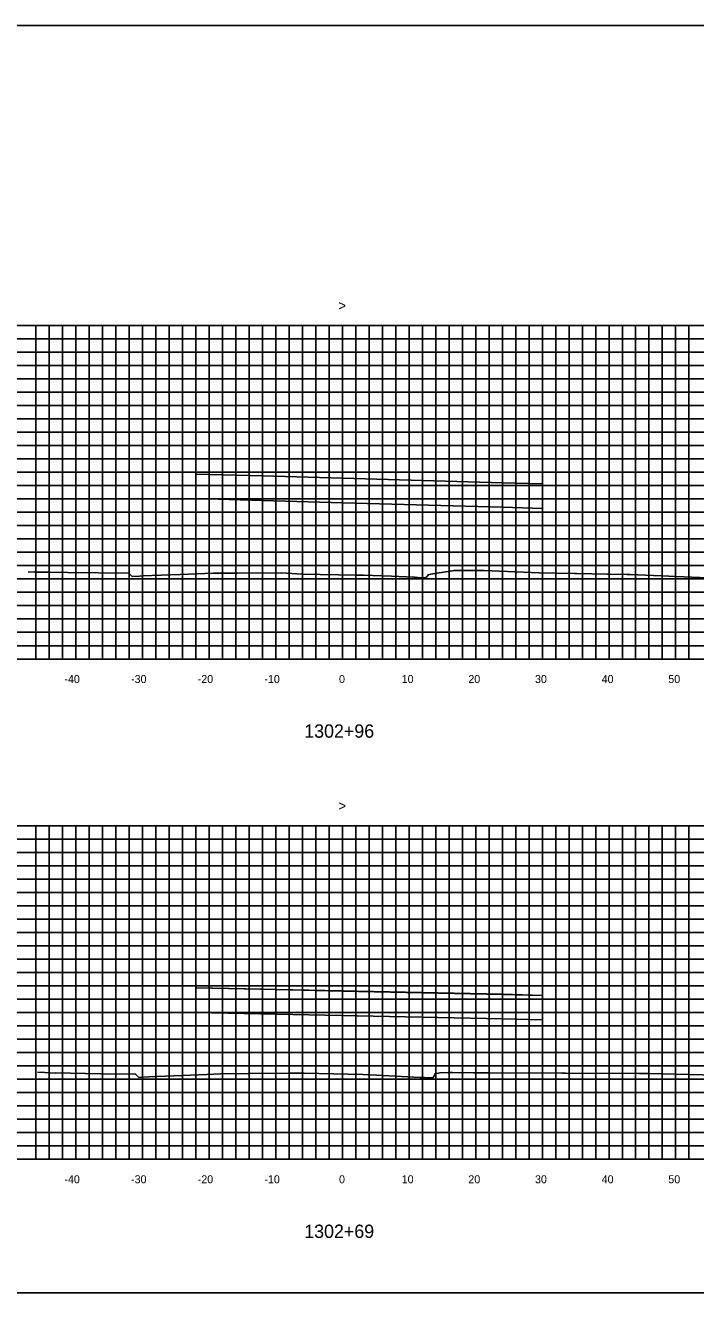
# Model space of a CAD drawing. Extents: x 1797714 to 1804825, y 249015 to 250269.
# Drawn here: x 1802923.4 to 1803024, y 250079.4 to 250269.4 of the extents above; entities that cross this region are included whole.
import ezdxf

# ---------------------------------------------------------------- set-up
doc = ezdxf.new("R2010")
doc.units = 0
for name, color, linetype in [('1', 7, 'Continuous'), ('10', 7, 'Continuous'), ('60', 7, 'Continuous'), ('BRG-DECK', 7, 'Continuous'), ('CL-CNST', 7, 'Continuous'), ('Level 62', 7, 'Continuous'), ('M-ROADS', 7, 'Continuous')]:
    doc.layers.add(name, color=color, linetype=linetype)

msp = doc.modelspace()

# ---------------------------------------------------------------- linework, layer by layer
for p, q in [((1802971, 250201.54), (1802971, 250203.54)), ((1802971, 250124.65), (1802971, 250126.65))]:
    msp.add_line(p, q)
msp.add_lwpolyline([(1802821, 250079.43), (1803121, 250079.43), (1803121, 250269.43), (1802821, 250269.43)], close=True)
at = {"layer": '60'}
for p, q in [((1802821, 250174.43), (1803121, 250174.43)), ((1802931, 250174.37), (1802931, 250174.43)), ((1802941, 250174.37), (1802941, 250174.43)), ((1802951, 250174.37), (1802951, 250174.43)), ((1802961, 250174.37), (1802961, 250174.43)), ((1802971, 250174.37), (1802971, 250174.43)), ((1802981, 250174.37), (1802981, 250174.43)), ((1802991, 250174.37), (1802991, 250174.43)), ((1803001, 250174.37), (1803001, 250174.43)), ((1803011, 250174.37), (1803011, 250174.43)), ((1803021, 250174.37), (1803021, 250174.43)), ((1802821, 250099.43), (1803121, 250099.43)), ((1802931, 250099.37), (1802931, 250099.43)), ((1802941, 250099.37), (1802941, 250099.43)), ((1802951, 250099.37), (1802951, 250099.43)), ((1802961, 250099.37), (1802961, 250099.43)), ((1802971, 250099.37), (1802971, 250099.43)), ((1802981, 250099.37), (1802981, 250099.43)), ((1802991, 250099.37), (1802991, 250099.43)), ((1803001, 250099.37), (1803001, 250099.43)), ((1803011, 250099.37), (1803011, 250099.43)), ((1803021, 250099.37), (1803021, 250099.43))]:
    msp.add_line(p, q, dxfattribs=at)
at = {"layer": 'BRG-DECK'}
for points in [[(1803001, 250197), (1803001, 250200.68), (1802995, 250200.86), (1802971, 250201.54), (1802959, 250201.88), (1802949, 250202.16), (1802949, 250198.48), (1802959, 250198.2), (1802971, 250197.86), (1802995, 250197.18)], [(1803001, 250120.31), (1803001, 250123.99), (1802995, 250124.17), (1802949, 250125.13), (1802949, 250121.45), (1802995, 250120.49)]]:
    msp.add_lwpolyline(points, close=True, dxfattribs=at)
at = {"layer": 'CL-CNST'}
for points in [[(1802949, 250202.16), (1802959, 250201.88), (1802971, 250201.54), (1802995, 250200.85), (1803001, 250200.68)], [(1802949, 250125.13), (1802959, 250124.91), (1802971, 250124.65), (1802995, 250124.12), (1803001, 250123.99)]]:
    msp.add_lwpolyline(points, dxfattribs=at)
at = {"layer": 'Level 62'}
for p, q in [((1802821, 250224.43), (1803121, 250224.43)), ((1802925, 250174.43), (1802925, 250224.43)), ((1802927, 250174.43), (1802927, 250224.43)), ((1802929, 250174.43), (1802929, 250224.43)), ((1802931, 250174.43), (1802931, 250224.43)), ((1802933, 250174.43), (1802933, 250224.43)), ((1802935, 250174.43), (1802935, 250224.43)), ((1802937, 250174.43), (1802937, 250224.43)), ((1802939, 250174.43), (1802939, 250224.43)), ((1802941, 250174.43), (1802941, 250224.43)), ((1802943, 250174.43), (1802943, 250224.43)), ((1802945, 250174.43), (1802945, 250224.43)), ((1802947, 250174.43), (1802947, 250224.43)), ((1802949, 250174.43), (1802949, 250224.43)), ((1802951, 250174.43), (1802951, 250224.43)), ((1802953, 250174.43), (1802953, 250224.43)), ((1802955, 250174.43), (1802955, 250224.43)), ((1802957, 250174.43), (1802957, 250224.43)), ((1802959, 250174.43), (1802959, 250224.43)), ((1802961, 250174.43), (1802961, 250224.43)), ((1802963, 250174.43), (1802963, 250224.43)), ((1802965, 250174.43), (1802965, 250224.43)), ((1802967, 250174.43), (1802967, 250224.43)), ((1802969, 250174.43), (1802969, 250224.43)), ((1802971, 250174.43), (1802971, 250224.43)), ((1802973, 250174.43), (1802973, 250224.43)), ((1802975, 250174.43), (1802975, 250224.43)), ((1802977, 250174.43), (1802977, 250224.43)), ((1802979, 250174.43), (1802979, 250224.43)), ((1802981, 250174.43), (1802981, 250224.43)), ((1802983, 250174.43), (1802983, 250224.43)), ((1802985, 250174.43), (1802985, 250224.43)), ((1802987, 250174.43), (1802987, 250224.43)), ((1802989, 250174.43), (1802989, 250224.43)), ((1802991, 250174.43), (1802991, 250224.43)), ((1802993, 250174.43), (1802993, 250224.43)), ((1802995, 250174.43), (1802995, 250224.43)), ((1802997, 250174.43), (1802997, 250224.43)), ((1802999, 250174.43), (1802999, 250224.43)), ((1803001, 250174.43), (1803001, 250224.43)), ((1803003, 250174.43), (1803003, 250224.43)), ((1803005, 250174.43), (1803005, 250224.43)), ((1803007, 250174.43), (1803007, 250224.43)), ((1803009, 250174.43), (1803009, 250224.43)), ((1803011, 250174.43), (1803011, 250224.43)), ((1803013, 250174.43), (1803013, 250224.43)), ((1803015, 250174.43), (1803015, 250224.43)), ((1803017, 250174.43), (1803017, 250224.43)), ((1803019, 250174.43), (1803019, 250224.43)), ((1803021, 250174.43), (1803021, 250224.43)), ((1803023, 250174.43), (1803023, 250224.43)), ((1802821, 250222.43), (1803121, 250222.43)), ((1802821, 250220.43), (1803121, 250220.43)), ((1802821, 250218.43), (1803121, 250218.43)), ((1802821, 250216.43), (1803121, 250216.43)), ((1802821, 250214.43), (1803121, 250214.43)), ((1802821, 250212.43), (1803121, 250212.43)), ((1802821, 250210.43), (1803121, 250210.43)), ((1802821, 250208.43), (1803121, 250208.43)), ((1802821, 250206.43), (1803121, 250206.43)), ((1802821, 250204.43), (1803121, 250204.43)), ((1802821, 250202.43), (1803121, 250202.43)), ((1802821, 250200.43), (1803121, 250200.43)), ((1802821, 250198.43), (1803121, 250198.43)), ((1802821, 250196.43), (1803121, 250196.43)), ((1802821, 250194.43), (1803121, 250194.43)), ((1802821, 250192.43), (1803121, 250192.43)), ((1802821, 250190.43), (1803121, 250190.43)), ((1802821, 250188.43), (1803121, 250188.43)), ((1802821, 250186.43), (1803121, 250186.43)), ((1802821, 250184.43), (1803121, 250184.43)), ((1802821, 250182.43), (1803121, 250182.43)), ((1802821, 250180.43), (1803121, 250180.43)), ((1802821, 250178.43), (1803121, 250178.43)), ((1802821, 250176.43), (1803121, 250176.43)), ((1802821, 250174.43), (1803121, 250174.43)), ((1802821, 250149.43), (1803121, 250149.43)), ((1802925, 250099.43), (1802925, 250149.43)), ((1802927, 250099.43), (1802927, 250149.43)), ((1802929, 250099.43), (1802929, 250149.43)), ((1802931, 250099.43), (1802931, 250149.43)), ((1802933, 250099.43), (1802933, 250149.43)), ((1802935, 250099.43), (1802935, 250149.43)), ((1802937, 250099.43), (1802937, 250149.43)), ((1802939, 250099.43), (1802939, 250149.43)), ((1802941, 250099.43), (1802941, 250149.43)), ((1802943, 250099.43), (1802943, 250149.43)), ((1802945, 250099.43), (1802945, 250149.43)), ((1802947, 250099.43), (1802947, 250149.43)), ((1802949, 250099.43), (1802949, 250149.43)), ((1802951, 250099.43), (1802951, 250149.43)), ((1802953, 250099.43), (1802953, 250149.43)), ((1802955, 250099.43), (1802955, 250149.43)), ((1802957, 250099.43), (1802957, 250149.43)), ((1802959, 250099.43), (1802959, 250149.43)), ((1802961, 250099.43), (1802961, 250149.43)), ((1802963, 250099.43), (1802963, 250149.43)), ((1802965, 250099.43), (1802965, 250149.43)), ((1802967, 250099.43), (1802967, 250149.43)), ((1802969, 250099.43), (1802969, 250149.43)), ((1802971, 250099.43), (1802971, 250149.43)), ((1802973, 250099.43), (1802973, 250149.43)), ((1802975, 250099.43), (1802975, 250149.43)), ((1802977, 250099.43), (1802977, 250149.43)), ((1802979, 250099.43), (1802979, 250149.43)), ((1802981, 250099.43), (1802981, 250149.43)), ((1802983, 250099.43), (1802983, 250149.43)), ((1802985, 250099.43), (1802985, 250149.43)), ((1802987, 250099.43), (1802987, 250149.43)), ((1802989, 250099.43), (1802989, 250149.43)), ((1802991, 250099.43), (1802991, 250149.43)), ((1802993, 250099.43), (1802993, 250149.43)), ((1802995, 250099.43), (1802995, 250149.43)), ((1802997, 250099.43), (1802997, 250149.43)), ((1802999, 250099.43), (1802999, 250149.43)), ((1803001, 250099.43), (1803001, 250149.43)), ((1803003, 250099.43), (1803003, 250149.43)), ((1803005, 250099.43), (1803005, 250149.43)), ((1803007, 250099.43), (1803007, 250149.43)), ((1803009, 250099.43), (1803009, 250149.43)), ((1803011, 250099.43), (1803011, 250149.43)), ((1803013, 250099.43), (1803013, 250149.43)), ((1803015, 250099.43), (1803015, 250149.43)), ((1803017, 250099.43), (1803017, 250149.43)), ((1803019, 250099.43), (1803019, 250149.43)), ((1803021, 250099.43), (1803021, 250149.43)), ((1803023, 250099.43), (1803023, 250149.43)), ((1802821, 250147.43), (1803121, 250147.43)), ((1802821, 250145.43), (1803121, 250145.43)), ((1802821, 250143.43), (1803121, 250143.43)), ((1802821, 250141.43), (1803121, 250141.43)), ((1802821, 250139.43), (1803121, 250139.43)), ((1802821, 250137.43), (1803121, 250137.43)), ((1802821, 250135.43), (1803121, 250135.43)), ((1802821, 250133.43), (1803121, 250133.43)), ((1802821, 250131.43), (1803121, 250131.43)), ((1802821, 250129.43), (1803121, 250129.43)), ((1802821, 250127.43), (1803121, 250127.43)), ((1802821, 250125.43), (1803121, 250125.43)), ((1802821, 250123.43), (1803121, 250123.43)), ((1802821, 250121.43), (1803121, 250121.43)), ((1802821, 250119.43), (1803121, 250119.43)), ((1802821, 250117.43), (1803121, 250117.43)), ((1802821, 250115.43), (1803121, 250115.43)), ((1802821, 250113.43), (1803121, 250113.43)), ((1802821, 250111.43), (1803121, 250111.43)), ((1802821, 250109.43), (1803121, 250109.43)), ((1802821, 250107.43), (1803121, 250107.43)), ((1802821, 250105.43), (1803121, 250105.43)), ((1802821, 250103.43), (1803121, 250103.43)), ((1802821, 250101.43), (1803121, 250101.43)), ((1802821, 250099.43), (1803121, 250099.43))]:
    msp.add_line(p, q, dxfattribs=at)
at = {"layer": 'M-ROADS'}
for points in [[(1802923.88, 250187.47), (1802924.76, 250187.51), (1802925.16, 250187.47), (1802926.89, 250187.43), (1802926.89, 250187.45), (1802929.81, 250187.4), (1802938.96, 250187.31), (1802939.07, 250187.18), (1802939.48, 250186.8), (1802940.56, 250186.85), (1802940.95, 250186.89), (1802946.66, 250187.11), (1802951.61, 250187.28), (1802955.25, 250187.32), (1802961.89, 250187.34), (1802964.91, 250187.15), (1802973.17, 250187), (1802973.29, 250187.01), (1802973.44, 250187), (1802973.73, 250187), (1802974.19, 250186.98), (1802978.38, 250186.87), (1802981.7, 250186.69), (1802981.89, 250186.68), (1802982.2, 250186.66), (1802982.3, 250186.63), (1802982.64, 250186.61), (1802982.94, 250186.61), (1802983.14, 250186.61), (1802983.18, 250186.61), (1802983.27, 250186.62), (1802983.32, 250186.59), (1802983.42, 250186.59), (1802983.7, 250186.82), (1802983.73, 250186.83), (1802983.79, 250186.89), (1802983.88, 250187.03), (1802983.88, 250187.07), (1802984.25, 250187.15), (1802984.88, 250187.26), (1802987.54, 250187.67), (1802987.73, 250187.69), (1802987.82, 250187.69), (1802988.2, 250187.69), (1802990.67, 250187.7), (1802992.05, 250187.68), (1802992.2, 250187.68), (1803000.5, 250187.35), (1803005.83, 250187.25), (1803006.14, 250187.24), (1803010.72, 250187.17), (1803010.89, 250187.16), (1803013.68, 250187.11), (1803014.13, 250187.11), (1803014.19, 250187.11), (1803026.94, 250186.57)], [(1802925.29, 250112.45), (1802925.8, 250112.47), (1802926.92, 250112.37), (1802927.91, 250112.35), (1802927.92, 250112.39), (1802934.77, 250112.26), (1802939.97, 250112.21), (1802940.22, 250111.92), (1802940.45, 250111.7), (1802941.06, 250111.73), (1802941.97, 250111.81), (1802950.67, 250112.16), (1802952.74, 250112.24), (1802956.89, 250112.28), (1802962.98, 250112.35), (1802965.25, 250112.32), (1802974.06, 250112.15), (1802976.1, 250112.06), (1802982.66, 250111.71), (1802983.3, 250111.67), (1802983.48, 250111.66), (1802983.78, 250111.64), (1802983.89, 250111.65), (1802983.95, 250111.65), (1802984.06, 250111.65), (1802984.24, 250111.65), (1802984.26, 250111.65), (1802984.29, 250111.65), (1802984.31, 250111.63), (1802984.33, 250111.64), (1802984.57, 250111.64), (1802984.61, 250111.68), (1802984.87, 250112.07), (1802984.87, 250112.22), (1802985.6, 250112.37), (1802985.66, 250112.37), (1802986.89, 250112.42), (1802986.97, 250112.42), (1802987.01, 250112.42), (1802987.46, 250112.42), (1802987.54, 250112.43), (1802990.67, 250112.41), (1802992.86, 250112.4), (1803003.96, 250112.33), (1803004.27, 250112.33), (1803004.45, 250112.33), (1803015.48, 250112.3), (1803016.37, 250112.3), (1803016.84, 250112.3), (1803016.86, 250112.3), (1803029.15, 250112.01)]]:
    msp.add_lwpolyline(points, dxfattribs=at)

# ---------------------------------------------------------------- texts
at = {"layer": '1'}
for s, p in [('1302+96', (1802965.28, 250162.63)), ('1302+69', (1802965.28, 250087.63))]:
    msp.add_text(s, height=2, dxfattribs=at).set_placement(p)
at = {"layer": '10'}
for s, p in [('-40', (1802929.3, 250170.83)), ('-30', (1802939.3, 250170.83)), ('-20', (1802949.3, 250170.83)), ('-10', (1802959.3, 250170.83)), ('0', (1802970.5, 250170.83)), ('10', (1802979.9, 250170.83)), ('20', (1802989.9, 250170.83)), ('30', (1802999.9, 250170.83)), ('40', (1803009.9, 250170.83)), ('50', (1803019.9, 250170.83)), ('-40', (1802929.3, 250095.83)), ('-30', (1802939.3, 250095.83)), ('-20', (1802949.3, 250095.83)), ('-10', (1802959.3, 250095.83)), ('0', (1802970.5, 250095.83)), ('10', (1802979.9, 250095.83)), ('20', (1802989.9, 250095.83)), ('30', (1802999.9, 250095.83)), ('40', (1803009.9, 250095.83)), ('50', (1803019.9, 250095.83))]:
    msp.add_text(s, height=1.2, dxfattribs=at).set_placement(p)
at = {"layer": '60'}
for p in [(1802970.39, 250226.68), (1802970.39, 250151.68)]:
    msp.add_text('>', height=1.5, dxfattribs=at).set_placement(p)

doc.saveas('drawing.dxf')
